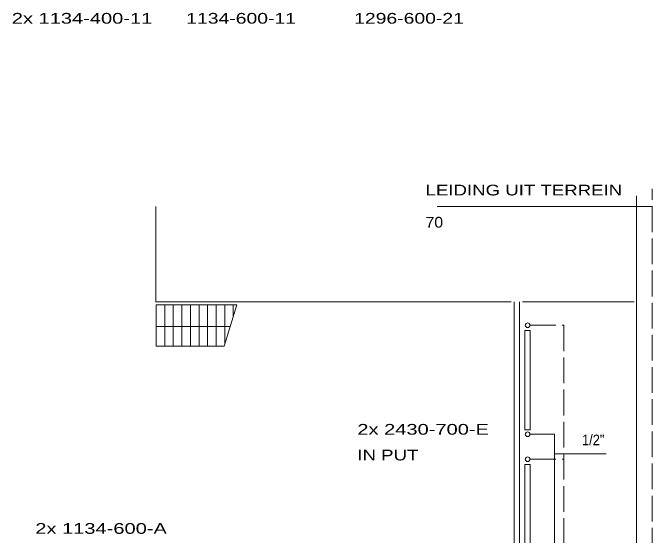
# Model space of a CAD drawing. Extents: x 295824 to 414724, y 24924 to 109024.
# Drawn here: x 321556 to 336476, y 48675 to 60860 of the extents above; entities that cross this region are included whole.
import ezdxf

# ---------------------------------------------------------------- set-up
doc = ezdxf.new("R2010")
doc.units = 0
doc.header["$LTSCALE"] = 100
doc.linetypes.add('LONG_DASHED', pattern=[7.5, 6, -1.5])
doc.layers.add('16', color=7, linetype='Continuous', lineweight=13)
doc.layers.add('61', color=7, linetype='Continuous', lineweight=13)

msp = doc.modelspace()

# ---------------------------------------------------------------- linework, layer by layer
at = {"layer": '16', "linetype": 'LONG_DASHED'}
for p, q in [((336475.7, 46746.4), (336475.7, 56755.7)), ((333624, 53571.2), (334414.3, 53571.2)), ((334414.3, 53571.2), (334414.3, 46333)), ((333624, 50447.1), (334414.3, 50447.1))]:
    msp.add_line(p, q, dxfattribs=at)
at = {"layer": '16'}
for p, q in [((336108.4, 46961.7), (336108.4, 56593.1)), ((336475.8, 56338.4), (331455.8, 56338.4)), ((333624, 51029.1), (334199, 51029.1)), ((334199, 51029.1), (334199, 46533)), ((334210.6, 50574.4), (335404.4, 50574.4))]:
    msp.add_line(p, q, dxfattribs=at)
for points in [[(333507, 53449.3), (333507, 51134.2), (333624.9, 51134.2), (333624.9, 53449.3)], [(333507, 50325.3), (333507, 48010.2), (333624.9, 48010.2), (333624.9, 50325.3)]]:
    msp.add_lwpolyline(points, close=True, dxfattribs=at)
for centre in [(333569.6, 53571.2), (333569.6, 51029.1), (333569.6, 50447.1)]:
    msp.add_circle(centre, 54.4, dxfattribs=at)
at = {"layer": '61'}
for p, q in [((324902, 53087.2), (324902, 54050.3)), ((325102, 53087.2), (325102, 54050.3)), ((325302, 53087.2), (325302, 54050.3)), ((325502, 53087.2), (325502, 54050.3)), ((325702, 53087.2), (325702, 54050.3)), ((325902, 53087.2), (325902, 54050.3)), ((326102, 53087.2), (326102, 54050.3)), ((326302, 53087.2), (326302, 54050.3)), ((326484.6, 53087.2), (326781.1, 54050.3)), ((326502, 53143.6), (326502, 54050.3)), ((326702, 53793.2), (326702, 54050.3)), ((333257, 47527.9), (333257, 54115.7)), ((333377, 54115.7), (333377, 47527.2)), ((336051.4, 54115.7), (333452, 54115.7)), ((324898.4, 53543.3), (326625, 53543.3)), ((324902, 53087.2), (326484.6, 53087.2))]:
    msp.add_line(p, q, dxfattribs=at)
for points in [[(333182, 54115.7), (324892.5, 54115.7), (324892.5, 56342.5)], [(326781.1, 54050.3), (324902, 54050.3), (324902, 53087.2)]]:
    msp.add_lwpolyline(points, dxfattribs=at)

# ---------------------------------------------------------------- texts
at = {"layer": '16'}
for s, width, p in [('2x 1134-400-11', 1.4, (321532.8, 60606)), ('1134-600-11', 1.35, (325603.8, 60606)), ('1296-600-21', 1.35, (329521.8, 60606)), ('LEIDING UIT TERREIN', 1.3, (331187.6, 56600)), ('70', 1.1, (331187.6, 55849.6)), ('2x 2430-700-E', 1.4, (329595.9, 51019.8)), ('1/2"', 0.9, (334836.2, 50772)), ('IN PUT', 1.3, (329595.9, 50419.8)), ('2x 1134-600-A', 1.4, (322081.4, 48707.4))]:
    msp.add_text(s, height=250, dxfattribs=dict(at, width=width)).set_placement(p)

doc.saveas('drawing.dxf')
